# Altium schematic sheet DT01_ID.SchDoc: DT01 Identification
size A4; DocumentNumber: 2; SheetNumber: 2; SheetTotal: 12
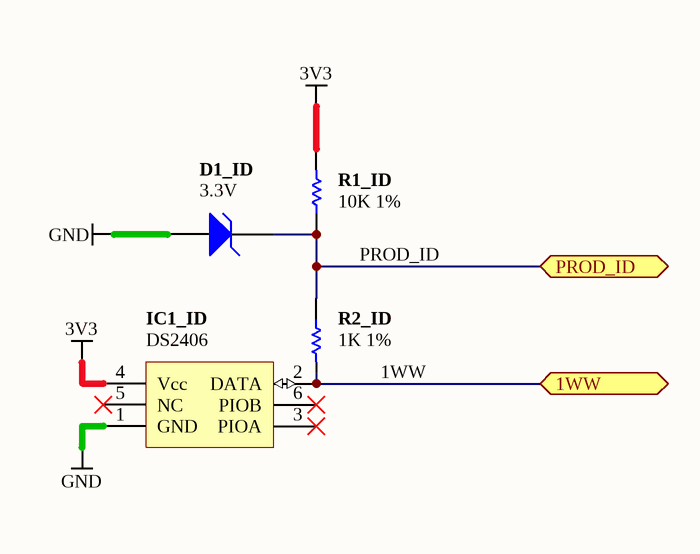
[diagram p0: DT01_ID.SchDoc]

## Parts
D1_ID  3.3V  [SOT95P230-3D]
IC1_ID  DS2406  [TSOC6]
R1_ID  10K 1%  [RESC1005-STAR]
R2_ID  1K 1%  [RESC1005-STAR]

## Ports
1WW (bidir), PROD_ID (bidir)

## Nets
3V3: IC1_ID.4(Vcc) R1_ID.2
GND: D1_ID.1(A) IC1_ID.1(GND)
1WW: IC1_ID.2(DATA) R2_ID.2 ; port 1WW
PROD_ID: D1_ID.2(K) R1_ID.1 R2_ID.1 ; port PROD_ID

Not connected (* = marked no-connect by the designer): IC1_ID 3(PIOA)* 5(NC)* 6(PIOB)*

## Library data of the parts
D1_ID = D-150-0005: Zener Diode, 3.3V; Max Forward Current: mA
IC1_ID = D-263-0002: Dual Addressable Switch Plus 1KB Memory; Bit Length: Bits; Speed: ps; Supply Voltage: mV
R1_ID = D-100-0130: Resistor, 10K 1% 0402 (1005); Power Rating: 63 mW
R2_ID = D-100-0121: Resistor, 1K 1% 0402 (1005); Power Rating: 63 mW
